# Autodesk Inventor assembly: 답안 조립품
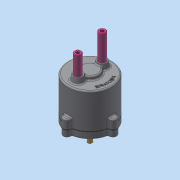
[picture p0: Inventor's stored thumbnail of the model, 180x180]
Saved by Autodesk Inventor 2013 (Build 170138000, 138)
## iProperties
Created: 2020-07
Part Number: 답안 조립품
Document SubType Name: Assembly
Designer: dgall
Mass: 1956.71 g
Surface Area: 1712.74 cm^2
Volume: 410.92 cm^3
Density: 4.76177 g/cm^3
Author: dgall
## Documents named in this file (14)
- C:\Users\dgall\Desktop\600706V1023\답안 조립품.iam
- C:\Users\dgall\Desktop\600706V1023\본체.ipt
- C:\Users\dgall\Desktop\600706V1023\개스킷.ipt
- C:\Users\dgall\Desktop\600706V1023\커버.ipt
- C:\Users\dgall\Desktop\600706V1023\볼트 M5.ipt
- C:\Users\dgall\Desktop\600706V1023\오일 실.ipt
- C:\Users\dgall\Desktop\600706V1023\가변스프링-1.ipt
- C:\Users\dgall\Desktop\600706V1023\가변스프링-2.ipt
- C:\Users\dgall\Desktop\600706V1023\멈춤링 10x1.ipt
- C:\Users\dgall\Desktop\600706V1023\멈춤링 22x1.2.ipt
- C:\Users\dgall\Desktop\600706V1023\메인 축.ipt
- C:\Users\dgall\Desktop\600706V1023\베어링 NA 4900.ipt
- C:\Users\dgall\Desktop\600706V1023\슬라이드 축.ipt
- C:\Users\dgall\Desktop\600706V1023\판캠.ipt
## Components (3 placed, 3 different names)
1. 개스킷:1
2. 가변스프링-1:1
3. 가변스프링-2:1
